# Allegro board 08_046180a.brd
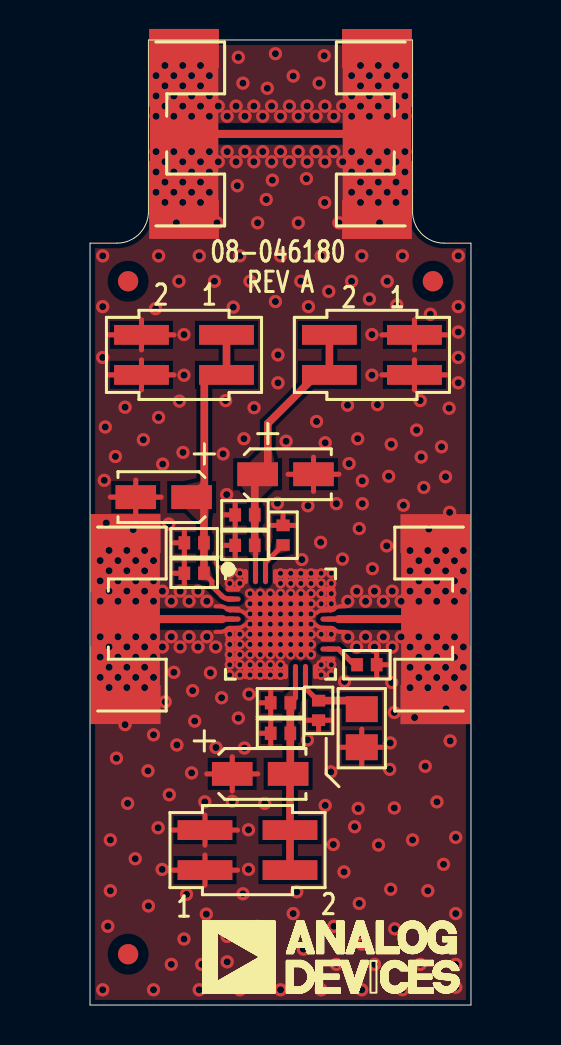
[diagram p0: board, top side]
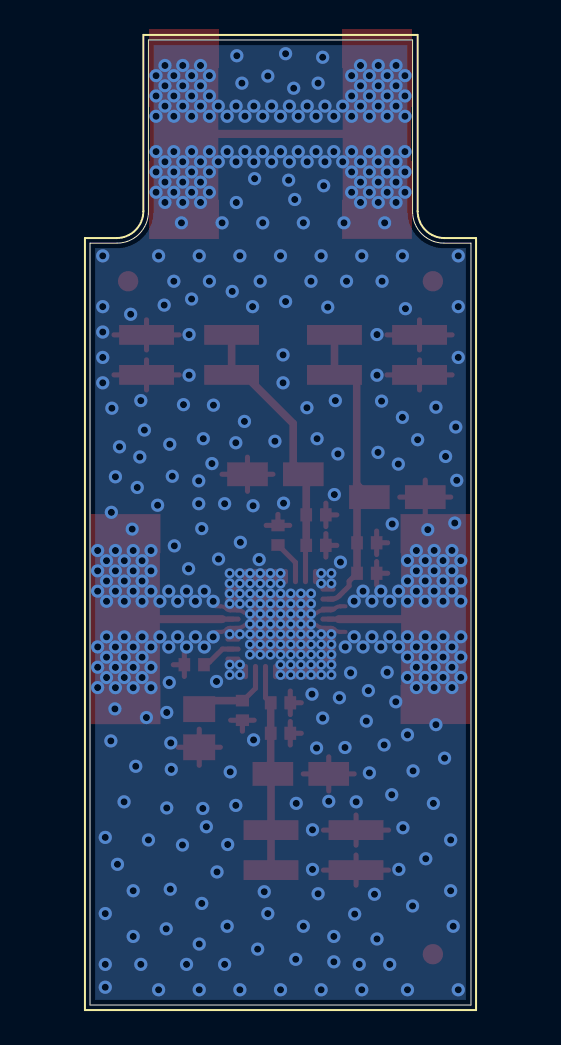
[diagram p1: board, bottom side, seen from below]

Outline 19.05 x 48.26 mm; copper layers: TOP, BOTTOM. Coordinates in mm from the lower left corner of the outline.
Outline path: 0,38.1 0,0 19.05,0 19.05,38.1 17.7,38.1 arc(16.59,38.56) 16.13,39.67 16.13,48.26 2.92,48.26 2.92,39.67 arc(2.46,38.56) 1.35,38.1 0,38.1

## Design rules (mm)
constraint set DEFAULT: min track width 0.254

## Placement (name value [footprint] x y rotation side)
C1  4.7uF  [C3216]  3.68 25.4 180 top
C2  0.01uF  [C0402]  5.21 23.11 180 top
C3  4.7uF  [C3216]  9.78 26.54 0 top
C4  100pF  [C0402]  5.21 21.59 180 top
C5  4.7uF  [C3216]  8.51 11.56 0 top
C6  0.01uF  [C0402]  7.75 24.51 180 top
C7  0.01uF  [C0402]  9.53 13.59 180 top
C8  100pF  [C0402]  7.75 22.99 180 top
C9  100pF  [C0402]  9.53 15.11 180 top
C10  100pF  [C0402]  9.65 23.5 90 top
C11  0.01uF  [C0402]  11.43 14.73 270 top
C12  4.7UF  [C0805H53]  13.59 13.84 270 top
C13  100pF  [C0402]  13.84 17.02 0 top
DUT1  ADL9005  [QFN32_5X5_PAD3X3]  9.53 19.05 270 top
J5  25-146-1000-92  [CNSMAL460W295H156]  2.92 43.56 180 top
J6  25-146-1000-92  [CNSMAL460W295H156]  16.13 43.56 0 top
NOREF  -  []  19.05 0 90 top
NOREF#2  -  []  -269.88 -336.55 0 top
NOREF#3  -  []  -3.17 -149.86 0 top
NOREF#4  -  []  0 0 90 top
NOREF#5  -  []  0 0 0 top
NOREF#6  -  []  0 0 0 top
NOREF#7  -  []  19.05 0 90 top
NOREF#8  -  []  9.53 57.15 0 top
NOREF#9  -  [unnamed#2]  17.14 36.2 0 top
NOREF#10  -  []  -0.13 19.3 0 top
NOREF#11  -  []  19.05 48.26 180 top
NOREF#12  -  []  0 48.26 270 top
NOREF#13  -  []  -128.52 -171.58 0 top
NOREF#14  -  []  -208.91 -128.91 0 top
NOREF#15  -  []  63.5 63.5 0 top
NOREF#16  -  []  -269.88 -336.55 0 top
NOREF#17  -  []  0 0 0 top
NOREF#18  -  []  -219.07 -158.75 0 top
NOREF#19  -  []  0 38.1 0 top
NOREF#20  -  []  161.93 69.85 0 top
NOREF#21  -  []  2.92 48.26 0 top
NOREF#22  -  []  16.47 38.69 0 top
NOREF#23  -  [unnamed#2]  1.91 2.54 0 top
NOREF#24  -  [unnamed#2]  1.91 36.2 0 top
NOREF#25  -  []  19.05 0 90 top
NOREF#26  -  []  -0.13 19.3 0 top
NOREF#27  -  []  115.32 -87.38 0 top
NOREF#28  -  []  170.94 43.43 180 bottom
NOREF#29  -  []  9.53 19.05 90 bottom
RFIN  25-146-1000-92  [CNSMAL460W295H156]  0 19.3 180 top
RFOUT  25-146-1000-92  [CNSMAL460W295H156]  19.05 19.3 0 top
VDD  87759-0414  [CNSMMHDR2X2L156W157H272]  14.1 32.51 270 top
VGG1  87759-0414  [CNSMMHDR2X2L156W157H272]  7.87 7.75 90 top
VGG2  87759-0414  [CNSMMHDR2X2L156W157H272]  4.7 32.51 270 top

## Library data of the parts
C1 C3 C5 = CAPP: Tolerance: N/A; User Part Number: UPN; alternate symbols: (); part number: CAPP_SM-4.7UF,N/A,N/A,E000691,C3216; tolerance: N/A
C2 C6 C7 C11 = CAP: Tolerance: 5; User Part Number: UPN; alternate symbols: (); part number: CAP_SM-0.01UF,25V,5,E020410,C0402; tolerance: 5
C4 C8-C10 C13 = CAP: Tolerance: 5; User Part Number: UPN; alternate symbols: (); part number: CAP_SM-100PF,50V,5,E023843,C0402; tolerance: 5
C12 = CAP: Tolerance: 10; User Part Number: UPN; alternate symbols: (); part number: CAP_SM-4.7UF,25V,10,E025752,C0805H53; tolerance: 10
DUT1 = ADL9005: User Part Number: UPN; Tolerance: N/A; alternate symbols: (); part number: ADL9005_SM-ADL9005,E028729,QFN32_5X5_PAD3X3; tolerance: N/A
J5 J6 RFIN RFOUT = CNBNC4P: Tolerance: N/A; User Part Number: UPN; alternate symbols: CNK38G62THK_EDGE; part number: CNBNC4P_SM-25-146-1000-92,E023346,CNSMAL460W295H156; tolerance: N/A
VDD VGG1 VGG2 = CN4P: User Part Number: UPN; Tolerance: N/A; alternate symbols: (); part number: CN4P_SM-87759-0414,E026270,CNSMMHDR2X2L156W157H272; tolerance: N/A

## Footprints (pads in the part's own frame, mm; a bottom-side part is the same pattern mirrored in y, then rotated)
C0402
  rect 0.584x0.66 smd: 1(-0.49,0) 2(0.49,0)
C0805H53
  rect 1.295x1.6 smd: 1(-0.953,0) 2(0.953,0)
C3216
  rect 2.032x1.194 smd: N(1.397,0) P(-1.397,0)
CNSMAL460W295H156
  custom 0.102x0.102 smd: 1(-1.549,0)
  custom 0.873x0.873 smd: 2(-1.778,-3.302) 3(-1.778,3.302)
  rect 3.429x8.56 smd: 4(-1.778,0)
CNSMMHDR2X2L156W157H272
  rect 0.991x2.743 smd: 1(-1.001,2.126) 2(-1.001,-2.126) 3(1.001,2.126) 4(1.001,-2.126)
QFN32_5X5_PAD3X3
  oval 0.254x0.762 smd: 1(-1.75,-2.375) 2(-1.25,-2.375) 3(-0.749,-2.375) 4(-0.249,-2.375) 5(0.249,-2.375) 6(0.749,-2.375) 7(1.25,-2.375) 8(1.75,-2.375) 17(1.75,2.375) 18(1.25,2.375) 19(0.749,2.375) 20(0.249,2.375) 21(-0.249,2.375) 22(-0.749,2.375) 23(-1.25,2.375) 24(-1.75,2.375)
  oval 0.762x0.254 smd: 9(2.375,-1.75) 10(2.375,-1.25) 11(2.375,-0.749) 12(2.375,-0.249) 13(2.375,0.249) 14(2.375,0.749) 15(2.375,1.25) 16(2.375,1.75) 25(-2.375,1.75) 26(-2.375,1.25) 27(-2.375,0.749) 28(-2.375,0.249) 29(-2.375,-0.249) 30(-2.375,-0.749) 31(-2.375,-1.25) 32(-2.375,-1.75)
  rect 2.997x2.997 smd: PAD(0,0)
unnamed#2
  round 1.016 smd: (0,0)

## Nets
GND: C1.N(N2) C2.2(N2) C3.N(N2) C4.2(N2) C5.P C6.2(N2) C7.2(N2) C8.2(N2) C9.2(N2) C10.2(N2) C11.2(N2) C12.2(N2) C13.2(N2) DUT1.1 DUT1.3 DUT1.5 DUT1.6 DUT1.7 DUT1.8 DUT1.9 DUT1.10 DUT1.11 DUT1.12 DUT1.13 DUT1.16 DUT1.17 DUT1.19 DUT1.20 DUT1.22 DUT1.23 DUT1.24 DUT1.25 DUT1.26 DUT1.27 DUT1.28 DUT1.29 DUT1.32 DUT1.PAD J5.2 J5.3 J5.4(SH3) J6.2 J6.3 J6.4(SH3) RFIN.2 RFIN.3 RFIN.4(SH3) RFOUT.2 RFOUT.3 RFOUT.4(SH3) VDD.1 VDD.3 VGG1.1 VGG1.3 VGG2.2 VGG2.4(N4)
UNNAMED_2_CAP_I4_N1: C1.P C2.1 C4.1 DUT1.2(VGG2) VGG2.1 VGG2.3
UNNAMED_2_CAP_I13_N1: C3.P C6.1 C8.1 DUT1.31 VDD.2 VDD.4(N4)
UNNAMED_2_CAP_I19_N1: C5.N(N2) C7.1 C9.1 DUT1.14 VGG1.2 VGG1.4(N4)
UNNAMED_2_CAP_I25_N1: C11.1 C12.1 DUT1.15
UNNAMED_2_CAP_I28_N1: C13.1 DUT1.18
UNNAMED_2_CAP_I29_N1: C10.1 DUT1.30
UNNAMED_2_CNBNC4P_I3_CNTR: DUT1.4 RFIN.1
UNNAMED_2_CNBNC4P_I8_CNTR: DUT1.21 RFOUT.1
UNNAMED_2_CNBNC4P_I32_CNTR: J5.1 J6.1

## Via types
v1: diameter 0.508, hole 0.254, TOP to BOTTOM, 93 vias
v2: diameter 0.66, hole 0.356, TOP to BOTTOM, 412 vias

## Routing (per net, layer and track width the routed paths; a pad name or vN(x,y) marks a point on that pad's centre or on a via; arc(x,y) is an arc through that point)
GND: length 67
  TOP w0.203: 12.78,18.66 12.52,18.66 arc(12.36,18.69) 12.22,18.79 arc(12.13,18.84) 12.03,18.86 11.67,18.86 arc(11.46,18.9) 11.28,19.02 ; 12.78,19.94 12.52,19.94 arc(12.36,19.91) 12.22,19.81 arc(12.13,19.76) 12.03,19.74 11.64,19.74 arc(11.47,19.7) 11.33,19.61 ; 6.27,18.66 6.53,18.66 arc(6.69,18.69) 6.83,18.79 arc(6.92,18.84) 7.02,18.86 7.39,18.86 arc(7.57,18.9) 7.72,19 ; 6.27,19.94 6.53,19.94 arc(6.69,19.91) 6.83,19.81 arc(6.92,19.76) 7.02,19.74 7.38,19.74 arc(7.58,19.7) 7.75,19.58
  TOP w0.254: 4.12,6.75 VGG1.1 ; VGG1.1 5.75,7.5 ; VGG1.1 5.75,5.99 ; VGG1.1 7.38,6.75 ; VGG2.4 2.57,32.26 ; VGG2.4 0.94,31.51 ; VGG2.4 2.57,30.76 ; VGG2.4 4.2,31.51 ; 9.03,13 C7.2 ; C7.2 8.49,13.59 ; C7.2 9.03,14.18 ; C8.2 7.26,23.57 ; C8.2 6.71,22.99 ; C8.2 7.26,22.4 ; 9.9,26.54 C3.N ; C3.N 11.18,25.69 ; C3.N 12.45,26.54 ; C3.N 11.18,27.4 ; VGG1.3 7.38,8.75 ; VGG1.3 5.75,8 ; VGG1.3 4.12,8.75 ; VGG1.3 5.75,9.5 ; C11.2 12.02,14.24 ; C11.2 10.84,14.24 ; C11.2 11.43,13.69 ; C13.2 14.88,17.02 ; C13.2 14.33,17.6 ; C13.2 14.33,16.43 ; VDD.1 17.85,33.51 ; VDD.1 16.22,34.26 ; VDD.1 14.59,33.51 ; VDD.1 16.22,32.76 ; 6.71,24.51 C6.2 ; C6.2 7.26,25.1 ; C6.2 7.26,23.92 ; C1.N 3.56,25.4 ; C1.N 2.29,24.55 ; C1.N 1.01,25.4 ; C1.N 2.29,26.25 ; C12.2 14.65,12.89 ; C12.2 13.59,13.79 ; C12.2 12.53,12.89 ; C12.2 13.59,11.99 ; 7.11,11.56 7.11,12.41 ; 7.11,11.56 8.38,11.56 ; 7.11,11.56 5.84,11.56 ; 7.11,11.56 7.11,10.7 ; 4.72,21 C4.2 ; C4.2 4.17,21.59 ; C4.2 4.72,22.18 ; C2.2 4.72,23.7 ; C2.2 4.72,22.53 ; C2.2 4.17,23.11 ; C10.2 9.65,24.53 ; C10.2 10.24,23.99 ; C10.2 9.07,23.99 ; 8.49,15.11 C9.2 ; C9.2 9.03,14.53 ; C9.2 9.03,15.7 ; 0.94,33.51 VGG2.2 ; VGG2.2 2.57,34.26 ; VGG2.2 4.2,33.51 ; VGG2.2 2.57,32.76 ; VDD.3 17.85,31.51 ; VDD.3 16.22,30.76 ; VDD.3 14.59,31.51 ; VDD.3 16.22,32.26
  vias: v1(6.99,21.59) v1(6.99,21.08) v1(6.99,18.54) v1(6.99,18.03) v1(6.99,17.53) v1(6.99,17.02) v1(6.99,16.51) v1(7.49,21.59) v1(7.49,21.08) v1(7.49,18.54) v1(7.49,18.03) v1(7.49,17.53) v1(7.49,17.02) v1(7.49,16.51) v1(8,20.57) v1(8,20.07) v1(8,19.56) v1(8,19.05) v1(8,18.54) v1(8,18.03) v1(8,17.53) v1(8,17.02) v1(8,16.51) v1(8.51,20.57) v1(8.51,20.07) v1(8.51,19.56) v1(8.51,19.05) v1(8.51,18.54) v1(8.51,18.03) v1(8.51,17.53) v1(8.51,17.02) v1(8.51,16.51) v1(9.02,20.57) v1(9.02,20.07) v1(9.02,19.56) v1(9.02,19.05) v1(9.02,18.54) v1(9.02,18.03) v1(9.02,17.53) v1(9.02,17.02) v1(9.02,16.51) v1(9.53,21.59) v1(9.53,21.08) v1(9.53,20.57) v1(9.53,20.07) v1(9.53,19.56) v1(9.53,19.05) v1(9.53,18.54) v1(9.53,18.03) v1(9.53,17.53) v1(9.53,17.02) v1(9.53,16.51) v1(10.03,21.59) v1(10.03,21.08) v1(10.03,20.57) v1(10.03,20.07) v1(10.03,19.56) v1(10.03,19.05) v1(10.03,18.54) v1(10.03,18.03) v1(10.03,17.53) v1(10.54,21.59) v1(10.54,21.08) v1(10.54,20.57) v1(10.54,20.07) v1(10.54,19.56) v1(10.54,19.05) v1(10.54,18.54) v1(10.54,18.03) v1(10.54,17.53) v1(11.05,21.59) v1(11.05,21.08) v1(11.05,20.57) v1(11.05,20.07) v1(11.05,19.56) v1(11.05,19.05) v1(11.05,18.54) v1(11.05,18.03) v1(11.05,17.53) v1(11.56,21.59) v1(11.56,21.08) v1(11.56,20.57) v1(11.56,20.07) v1(11.56,18.54) v1(11.56,17.02) v1(11.56,16.51) v1(12.07,21.59) v1(12.07,21.08) v1(12.07,20.57) v1(12.07,20.07) v1(12.07,18.54) v1(12.07,17.02) v1(12.07,16.51) v2(0.51,22.23) v2(0.51,21.21) v2(0.51,20.19) v2(0.51,18.41) v2(0.51,17.4) v2(0.51,16.38) v2(0.63,37.47) v2(0.63,34.92) v2(0.63,32.39) v2(0.63,0.76) v2(0.76,28.91) v2(0.71,26.24) v2(0.81,24.1) v2(0.95,22.73) v2(0.95,21.72) v2(0.95,20.7) v2(0.95,17.91) v2(0.95,16.89) v2(0.95,15.88) v2(0.89,3.94) v2(1.02,8.26) v2(1.02,5.71) v2(1.27,27.43) v2(1.32,12.34) v2(1.4,22.23) v2(1.4,21.21) v2(1.4,20.19) v2(1.4,18.41) v2(1.4,17.4) v2(1.4,16.38) v2(1.75,29.9) v2(1.75,14.02) v2(1.84,22.73) v2(1.84,21.72) v2(1.84,20.7) v2(1.84,17.91) v2(1.84,16.89) v2(1.84,15.88) v2(1.88,10.08) v2(2.16,23.77) v2(2.26,7.32) v2(2.29,22.23) v2(2.29,21.21) v2(2.29,20.19) v2(2.29,18.41) v2(2.29,17.4) v2(2.29,16.38) v2(2.67,28.27) v2(2.73,22.73) v2(2.73,21.71) v2(2.73,20.7) v2(2.73,17.91) v2(2.73,16.89) v2(2.73,15.88) v2(2.9,11.71) v2(2.92,4.95) v2(3.18,22.23) v2(3.18,21.21) v2(3.18,20.19) v2(3.18,18.41) v2(3.18,17.4) v2(3.18,16.38) v2(3.18,13.51) v2(3.18,0.76) v2(3.3,46.48) v2(3.3,45.46) v2(3.3,44.44) v2(3.3,42.68) v2(3.3,41.66) v2(3.3,40.65) v2(3.28,34.82) v2(3.43,37.47) v2(3.43,29.39) v2(3.4,8.86) v2(3.63,27.05) v2(3.62,20.7) v2(3.62,17.91) v2(3.61,6.78) v2(3.75,46.98) v2(3.75,45.97) v2(3.75,44.95) v2(3.75,42.17) v2(3.75,41.15) v2(3.75,40.14) v2(3.76,15.16) v2(3.94,24.05) v2(3.96,10.52) v2(4.06,20.19) v2(4.06,18.41) v2(4.06,2.03) v2(4.19,46.48) v2(4.19,45.46) v2(4.19,44.44) v2(4.19,42.68) v2(4.19,41.66) v2(4.19,40.65) v2(4.19,16.64) v2(4.32,39.12) v2(4.34,13) v2(4.45,36.2) v2(4.47,30.2) v2(4.51,20.7) v2(4.51,17.91) v2(4.64,46.98) v2(4.64,45.97) v2(4.64,44.95) v2(4.64,42.17) v2(4.64,41.15) v2(4.64,40.14) v2(4.65,27.64) v2(4.7,33.53) v2(4.7,31.5) v2(4.7,3.3) v2(4.83,5.54) v2(4.95,20.19) v2(4.95,18.41) v2(5.08,46.48) v2(5.08,45.46) v2(5.08,44.44) v2(5.08,42.68) v2(5.08,41.66) v2(5.08,40.65) v2(5.13,15.72) v2(5.08,11.61) v2(5.23,14.2) v2(5.46,37.47) v2(5.4,20.7) v2(5.4,17.91) v2(5.46,0.76) v2(5.52,46.98) v2(5.52,45.97) v2(5.52,44.95) v2(5.52,42.17) v2(5.52,41.15) v2(5.52,40.14) v2(5.59,2.03) v2(5.74,10.16) v2(5.84,20.19) v2(5.84,18.41) v2(5.82,4.55) v2(5.97,46.48) v2(5.97,45.46) v2(5.97,44.44) v2(5.97,42.68) v2(5.97,41.66) v2(5.97,40.65) v2(6.02,16.61) v2(6.22,36.2) v2(6.35,39.12) v2(6.29,17.91) v2(6.3,12.88) v2(6.41,44.95) v2(6.41,42.17) v2(6.53,22.15) v2(6.65,27.56) v2(6.58,15.37) v2(6.86,44.44) v2(6.86,42.68) v2(6.78,30.23) v2(6.83,25.53) v2(6.86,3.43) v2(6.86,2.16) v2(7.16,34.9) v2(7.11,10.19) v2(7.3,44.95) v2(7.3,42.17) v2(7.37,40.97) v2(7.42,47.4) v2(7.42,14.35) v2(7.49,37.47) v2(7.49,0.76) v2(7.65,46.1) v2(7.65,5.56) v2(7.75,44.44) v2(7.75,42.68) v2(7.7,28.32) v2(7.72,12.85) v2(7.95,15.54) v2(7.92,8.76) v2(7.92,6.78) v2(8,36.2) v2(8.19,44.95) v2(8.19,42.17) v2(8.2,29.87) v2(8.38,39.12) v2(8.38,3.94) v2(8.64,44.44) v2(8.64,42.68) v2(8.74,10.08) v2(8.76,2.29) v2(8.86,45.85) v2(8.81,40.28) v2(9.08,44.95) v2(9.08,42.17) v2(9.12,41.25) v2(9.27,47.57) v2(9.27,35.18) v2(9.37,25.1) v2(9.4,32.51) v2(9.4,31.12) v2(9.53,44.44) v2(9.53,42.68) v2(9.53,37.47) v2(9.53,0.76) v2(9.8,28.19) v2(9.97,44.95) v2(9.97,42.17) v2(10.16,46.46) v2(10.16,4.57) v2(10.34,5.66) v2(10.41,44.44) v2(10.41,42.68) v2(10.41,39.12) v2(10.54,36.2) v2(10.59,22.28) v2(10.67,2.79) v2(10.86,44.95) v2(10.86,42.17) v2(10.82,41.33) v2(10.87,13.26) v2(10.92,34.92) v2(10.9,24.97) v2(11.3,44.44) v2(11.3,42.68) v2(11.33,29.18) v2(11.46,46.1) v2(11.56,37.47) v2(11.53,23.14) v2(11.56,0.76) v2(11.71,47.47) v2(11.75,44.95) v2(11.75,42.17) v2(11.73,40.13) v2(11.76,28.12) v2(11.76,9.98) v2(11.94,35.69) v2(12.04,11.66) v2(12.17,8.03) v2(12.19,44.44) v2(12.19,42.68) v2(12.19,3.94) v2(12.32,25.07) v2(12.32,2.03) v2(12.45,39.12) v2(12.64,44.95) v2(12.64,42.17) v2(12.62,22.3) v2(12.73,16.18) v2(12.7,6.65) v2(12.88,30) v2(12.95,27.08) v2(12.89,20.19) v2(12.89,18.41) v2(13.08,46.48) v2(13.08,45.46) v2(13.08,44.44) v2(13.08,42.68) v2(13.08,41.66) v2(13.08,40.65) v2(13.08,36.2) v2(13.23,8.92) v2(13.34,20.7) v2(13.34,17.9) v2(13.39,28.32) v2(13.46,23.83) v2(13.41,9.83) v2(13.46,5.08) v2(13.53,46.98) v2(13.53,45.97) v2(13.53,44.95) v2(13.53,42.17) v2(13.53,41.15) v2(13.53,40.14) v2(13.59,37.47) v2(13.61,26.21) v2(13.61,25.07) v2(13.59,3.05) v2(13.59,0.76) v2(13.78,20.19) v2(13.78,18.41) v2(13.97,46.48) v2(13.97,45.46) v2(13.97,44.44) v2(13.97,42.68) v2(13.97,41.66) v2(13.97,40.65) v2(13.97,35.31) v2(14.1,33.53) v2(14.1,31.5) v2(14.12,21.82) v2(14.22,20.7) v2(14.22,17.9) v2(14.22,2.03) v2(14.41,46.98) v2(14.41,45.97) v2(14.41,44.95) v2(14.41,42.17) v2(14.41,41.15) v2(14.41,40.14) v2(14.38,30.02) v2(14.43,8) v2(14.48,39.12) v2(14.67,20.19) v2(14.67,18.41) v2(14.86,46.48) v2(14.86,45.46) v2(14.86,44.44) v2(14.86,42.68) v2(14.86,41.66) v2(14.86,40.65) v2(14.86,36.2) v2(14.83,22.96) v2(14.94,26.44) v2(15.06,28.04) v2(15.01,13.11) v2(14.99,11.79) v2(15.04,5.79) v2(15.11,20.7) v2(15.11,17.9) v2(15.09,16.13) v2(15.21,14.63) v2(15.21,9.86) v2(15.24,3.81) v2(15.3,46.98) v2(15.3,45.97) v2(15.3,44.95) v2(15.3,42.17) v2(15.3,41.15) v2(15.3,40.14) v2(15.34,35) v2(15.56,20.19) v2(15.56,18.41) v2(15.62,37.47) v2(15.67,24.99) v2(15.62,0.76) v2(15.75,46.48) v2(15.75,45.46) v2(15.75,44.44) v2(15.75,42.68) v2(15.75,41.66) v2(15.75,40.65) v2(16,22.73) v2(16,21.71) v2(16,20.7) v2(16,17.9) v2(16,16.89) v2(16,15.87) v2(16.13,8.26) v2(16.23,14.38) v2(16.33,28.75) v2(16.45,22.22) v2(16.45,21.2) v2(16.45,20.19) v2(16.45,18.41) v2(16.45,17.39) v2(16.45,16.38) v2(16.51,30.23) v2(16.56,27.41) v2(16.51,2.03) v2(16.69,25.88) v2(16.76,11.94) v2(16.94,23.8) v2(16.89,22.73) v2(16.89,21.71) v2(16.89,20.7) v2(16.89,17.9) v2(16.89,16.89) v2(16.89,15.87) v2(16.89,5.71) v2(16.89,3.43) v2(17.02,34.54) v2(17.34,22.22) v2(17.34,21.2) v2(17.34,20.19) v2(17.34,18.41) v2(17.34,17.39) v2(17.34,16.38) v2(17.35,10.16) v2(17.58,27.91) v2(17.68,7.04) v2(17.78,26.42) v2(17.78,22.73) v2(17.78,21.71) v2(17.78,20.7) v2(17.78,17.9) v2(17.78,16.89) v2(17.78,15.87) v2(17.81,14.81) v2(17.96,29.84) v2(17.98,24.64) v2(18.01,13.21) v2(18.22,22.22) v2(18.22,21.2) v2(18.22,20.19) v2(18.22,18.41) v2(18.22,17.39) v2(18.22,16.38) v2(18.29,8.38) v2(18.29,4.57) v2(18.29,2.03) v2(18.29,0.89) v2(18.41,37.47) v2(18.41,34.92) v2(18.41,33.66) v2(18.41,32.39) v2(18.41,31.12) v2(18.67,22.73) v2(18.67,21.71) v2(18.67,20.7) v2(18.67,17.91) v2(18.67,16.89) v2(18.67,15.88)
UNNAMED_2_CAP_I4_N1: length 15.6
  TOP w0.254: C4.1 6.09,21.19 6.09,20.96 6.59,20.46 arc(6.77,20.34) 6.97,20.3 DUT1.2
  TOP w0.381: C4.1 C2.1 5.7,25.02 5.31,25.4 C1.P 5.71,26.04 5.71,31.13 6.1,31.51 VGG2.3 VGG2.1
UNNAMED_2_CAP_I13_N1: length 14
  TOP w0.254: C8.1 8.28,22.95 DUT1.31
  TOP w0.381: C8.1 C6.1 8.24,26.4 C3.P 8.89,27.05 8.89,29.08 11.32,31.51 VDD.4 VDD.2
UNNAMED_2_CAP_I19_N1: length 10.1
  TOP w0.254: C9.1 10.27,15.37 DUT1.14
  TOP w0.381: C9.1 C7.1 10.02,11.67 C5.N 10,11.46 VGG1.4 VGG1.2
UNNAMED_2_CAP_I25_N1: length 4.1
  TOP w0.254: C11.1 11.39,15.22 10.77,15.84 DUT1.15
  TOP w0.381: C12.1 13.16,15.22 C11.1
UNNAMED_2_CAP_I28_N1: length 1.8
  TOP w0.254: C13.1 13.23,17.14 13.08,17.14 12.43,17.8 DUT1.18
UNNAMED_2_CAP_I29_N1: length 1.9
  TOP w0.254: 9.65,23 8.78,22.13 DUT1.30
UNNAMED_2_CNBNC4P_I3_CNTR: length 5.6
  TOP w0.254: 6.61,19.3 DUT1.4
  TOP w0.406: RFIN.1 6.61,19.3
UNNAMED_2_CNBNC4P_I8_CNTR: length 5.6
  TOP w0.254: 12.44,19.3 DUT1.21
  TOP w0.406: RFOUT.1 12.44,19.3
UNNAMED_2_CNBNC4P_I32_CNTR: length 10.1
  TOP w0.406: J5.1 J6.1

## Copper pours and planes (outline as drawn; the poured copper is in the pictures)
GND on TOP, BOTTOM: 15.88,48.01 15.88,39.67 16.41,38.38 17.7,37.85 18.8,37.85 18.8,0.25 0.25,0.25 0.25,37.85 1.35,37.85 2.64,38.38 3.18,39.67 3.18,48.01

Small or netless copper shapes (teardrops, artwork), in the pictures only: 19 on TOP

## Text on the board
Ref Des/Silkscreen Top: 08-046180 | REV A
PAGE_OUTLINE: A1 | CHANGE PER ECR-081910 | 25SEP18 | J.B.
DIMENSION: TYP | CONNECTOR WIDTH 4 PL | CENTER CONDUCTOR TO SHORT | SEE NOTE 15
User.15: AUTO-HANDLER ENGINEERING INPUT | REFERENCE/EVALUATION DESIGN: | Previous designs can provide guidance in the layout of the board. or provide | a starting point to note differences. | MAXIMUM FREQUENCIES: | RF net frequencies will determine the connectors to use. | ARE THRU CAL NETS required? | MAXIMUM CURRENT REQUIREMENTS of voltage nets. | COMMUNICATE: | Review anticipated stack-up, materials, trace/space/mask for RF, stiffener, | etch matching, edge plating, via fill, etc. | CONNECTOR SELECTION: | Given a max frequency any connector of that rating or above may be selected. | The lower frequency connectors are generally lower cost and are usually easier | to install. A mix of RF connectors is allowed. | STIFFENER SELECTION: (Allegro symbol prefix adch_plate...) | M025215 adch_plate_hf_ext_cassini_03-052988.bsm (Plus future flange mount designs) | Is used with the flanged RF connectors cnsma19g_flange and cnsma30g_flange. | The 19g connector, board thickness of .032 +/-10% or less and up to 4 layers. | The 20-30g connector, uses a 10mil core or less dielectric and has 2 layers. | The board outline is to match this plate outline. Bottom layer is to be ground. | M024984 adch_plate_hf_ext_cassini_03-052985.bsm (Plus future non flange mount) | Is used with any of the frequency listed RF edge connectors for 62 thick boards. | Board thickness is to be .062 +/- 10%, with 4 or more layers. Bottom layer is | to be ground. The board outline at a minimum must cover the plate outline, and | is to be expanded to allow for the placement of the RF connectors in an area | clear of the contactor, handler arm arc, and the stiffener plate. | PLACEMENT AND ROUTING CONSIDERATIONS: | The autohandler plate is to be placed mirrored at X=0 Y=0 zero rotation.(per notes) | The Ismeca_handler_ko.bsm Is to be placed at X=0 Y=0 zero rotation. | The contactor to be specified by manufacturing engineering in the HLM Forum. | Locate contactor at X=0 Y=0 rotated to have pin 1 to the upper left (NW quadrant.) | To mount flanged RF connectors first display Package Geometry/Referance and | /Assembly Bottom. Place each at a center circle (with the cross) of a three circle | mounting hole pattern indicator. Orient to cover the outside reference pattern | circles. Choose the location that makes the shortest RF connection or if part of a | matched RF pair choose the circles that accomodate the best matching trace pattern. | Locate RF edge launch connectors at points that allow for clean short routing that | clears the contactor boundary, Ismecca_handler_ko, and the autohandler stiffener. | Their placement should consider matched length requirements that does not encroach | on the contactor arms having via fencing along their sides. Keep in mind that the | connector outline edges will have to incorporate into the Board Geometry/Outline. | RF ROUTING, Use the material, trace width and space in the connector symbol notes. | Layout pattern should resemble that of the respective EVAL board layout. | RF lines ideally to be symmetrical, straight and as short as possible. Neck down to | IC pad width as close to pin as possible. Pad stacks on RF trace may be adjusted | to the width of the RF trace if less than 10 mils, otherwise add fillets. | Curves on RF lines require a minimum radius 3 times the trace width. | (Greater than 3X is preferred.) | GND-VIA fence to be along each side of RF lines, via edge to be close to the GND | plane edge. Do not encroach into the etch to trace spacing. | Continuous GND edge is desired along RF paths, keep RF to RF and RF to DC lines | separated by GND if possible. Connect GND pins adjacent to RF pins to GND plane. | THRU CAL NETS:Are they required? How is their length to be determined? | The default is CAL lines will have the same components mounted at the same | intervals as the RF trace it represents. (Ideally copy the full trace component | and via structure, and swap in the through cal components.) | DC TRACES: Non critical signal trace width is typically 10mils. | Voltages are preferably in planes, if routed they must be sized to handle the | maximum current requirements. (Search web "PCB current capacity calculator") | VIAS: GND within pads use VIA2510 other signal power and ground use VIA2814. | Blind and burried vias also to have 14 drill and 28 pad. Filled vias are not | recommended for Auto-handler designs. Shape connection to be full contact. | If thru non GND signal vias are used, they are to be covered by bottom side solder- | mask (pad+2x gap+10mils min.). Unless these vias are on a 62 mil board and the via | is more than 20 mils away from the stiffener plate. | (A positive bottom mask may need to be generated.) | CONNECTOR NAMING | CONNECTOR TYPE | FREQUENCY | PREFIX | CNSMA20G62THK_EDGE | MOUNTING FORM | BOARD THICKNESS | GND AND POWER PLANES: | Add ground pour to all non power plane layers. Take care not to create thin ground | shapes between signals without vias on the top layer that will act as antena. | GND planes for the width of the edge connectors to be 3 mils from the outline, | unless the connector specifies edge plating is required. Signals and planes in all | other areas to be 10 mil minimum from board outline. | Thermal relief for edge connector GND pins and all Dut pins to be full contact. | Thermal relief for other pins to be a nominal 10 mils by 4 spokes, adjustments may | be made for pins with less spokes. | STIFFENER | 03-052988 | 03-052985 | STACKUP | 2_LYR6-6R4350B | 2_LYR10R4350B | 4_LYR10R4350B-T0P | THICKNESS | ~9MILS | ~12MILS | <32MILS +/- 10% | 62MILS +/-10% | CONNECTOR/FREQUENCY | CNSMA30G_FLANGE | CNSMA19G_FLANGE | CNSMA10G62THK_EDGE | CNK38G62THK_EDGE | CNK40G62THK_EDGE | CN2_4MM50G62THK_EDGE | CN2_4MM50G62THK_LP_EDGE
User.20: J.BEDROSIAN | 03/2017 | CHANGE PER ECR-081910 | A1 | 25SEP18 | J.B.
User.25: FIGURE | SIZE | 10.0 | 14.0 | PLATED | FINISHED HOLES IN MILS | ALL UNITS ARE IN MILS | QTY | 93 | 412 | TOLERANCE/NOTES
